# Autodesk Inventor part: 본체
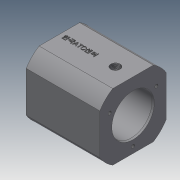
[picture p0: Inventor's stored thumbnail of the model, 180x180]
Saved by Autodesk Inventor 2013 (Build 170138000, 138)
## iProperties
Created: 2020-02
Part Number: 본체
Material: Generic
Document SubType Name: Modeling
Designer: user
Density: 1 g/cm^3
Author: user
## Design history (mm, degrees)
sketch "스케치1"
  geometry: L1 (-32, -32)-(32, -32); L2 (32, -32)-(32, 32); L3 (32, 32)-(-32, 32); L4 (-32, 32)-(-32, -32); L5 (-32, -32)-(32, 32); L6 (32, -32)-(-32, 32); 1 further point
  constraints: 12 end point, 2 midpoint, 2 parallel, 1 horizontal, 1 perpendicular
  dimensions: "d0" = 64 distance of L3.end L2.end; "d1" = 64 distance of L1.end L2.end
extrude "돌출1" new body sketch "스케치1" distance "d2" = 71; taper "d3" = 0 deg
sketch "스케치2"
  geometry: C1 r 14 at (0, 0); 1 further point
  constraints: 1 centre point, 1 coincident
  dimensions: "d4" = 28 diameter of C1
extrude "돌출2" join sketch "스케치2" distance "d5" = 12; taper "d6" = 0 deg
chamfer "모따기1" distance "d7" = 1; stored, may be unused: second distance "d8" = 2, angle "d9" = 45 deg
sketch "스케치3"
  geometry: C1 r 37.5 at (0, 0); 1 further point
  constraints: 1 centre point, 1 coincident
  dimensions: "d10" = 75 diameter of C1
extrude "돌출3" sketch "스케치3" distance "d11" = 83; taper "d12" = 0 deg
sketch "스케치4"
  geometry: C1 r 20 at (0, 0); A1 r 37.5 centre (0, 0) between (32, 19.551) and (19.551, 32) reference
  constraints: 1 centre point, 1 coincident
  dimensions: "d13" = 40 diameter of C1
extrude "돌출4" cut sketch "스케치4" distance "d14" = 62; taper "d15" = 0 deg
chamfer "모따기2" distance "d16" = 1.8; stored, may be unused: second distance "d17" = 2, angle "d18" = 15 deg
sketch "스케치5"
  geometry: L1 (0, 0)-(0, -26); C1 r 20.482 at (0, 0) reference; A1 r 37.5 centre (0, 0) between (-19.551, 32) and (-32, 19.551) reference; 1 further point
  constraints: 2 end point, 1 coincident, 1 vertical alignment
  dimensions: "d19" = 26 distance of L1.start L1.end
hole "구멍1" sketch "스케치5" at (0, -26) diameter "d20" = 3.242; stored, may be unused: countersink angle "d24" = 90 deg, drill point angle "d26" = 118 deg; dims "d21" = 10, "d22" = 4, "d23" = 2, "d25" = 12
sketch "스케치6"
  geometry: L1 (32, -19.551)-(32, 19.551) reference; L2 (0, 0)-(0, 26); C1 r 14 at (0, 0) reference; 1 further point
  constraints: 2 end point, 1 coincident, 1 parallel
  dimensions: "d30" = 26 distance of L2.start L2.end
hole "구멍2" sketch "스케치6" at (0, 26) diameter "d31" = 3.242; stored, may be unused: countersink angle "d35" = 90 deg, drill point angle "d37" = 118 deg; dims "d32" = 10, "d33" = 4, "d34" = 2, "d36" = 12
sketch "스케치7"
  geometry: C1 r 13 at (0, 0) reference; C2 r 2 at (0, 0)
  constraints: 1 centre point, 1 coincident
  dimensions: "d41" = 4 diameter of C2
extrude "돌출5" cut sketch "스케치7" stored distance "d42" = 62; taper "d43" = 0 deg
sketch "스케치8"
  geometry: C1 r 13 at (0, 0) reference; 1 further point
  constraints: 1 coincident
hole "구멍3" sketch "스케치8" at (0, 0) diameter "d44" = 8.917; stored, may be unused: countersink angle "d48" = 90 deg, drill point angle "d50" = 118 deg; dims "d45" = 14, "d46" = 4, "d47" = 2, "d49" = 17
sketch "스케치9"
  geometry: L1 (39.102, 0)-(0, 0) reference; 3 further points
  constraints: 1 midpoint, 1 vertical alignment
  dimensions: "d51" = 17 distance of point (19.551, 0) point (19.551, -17)
hole "구멍4" sketch "스케치9" at (19.551, -17) diameter "d52" = 8.917; stored, may be unused: countersink angle "d56" = 90 deg, drill point angle "d58" = 118 deg; dims "d53" = 6, "d54" = 4, "d55" = 2, "d57" = 9
sketch "스케치10"
  geometry: C1 r 4.458 at (19.551, -17) reference; C2 r 2 at (19.551, -17); 1 further point
  constraints: 1 centre point, 1 coincident
  dimensions: "d59" = 4 diameter of C2
extrude "돌출6" cut sketch "스케치10" stored distance "d60" = 62; taper "d61" = 0 deg
sketch "스케치11"
  geometry: L1 (39.102, 0)-(0, 0) reference; L2 (0, -71)-(-12.449, -71) reference; 3 further points
  constraints: 1 midpoint, 1 vertical alignment, 1 other
  dimensions: "d62" = 20 vertical distance of L2.end point (19.551, -51)
feature "엠보싱1" sketch "스케치11" dims "d0" = 64, "d1" = 64, "d63" = 0.5, "d64" = 0
node "솔리드1"
pattern_circular "원형 패턴1" dims angle "d28" = 360 deg
pattern_circular "원형 패턴2" dims angle "d39" = 360 deg
